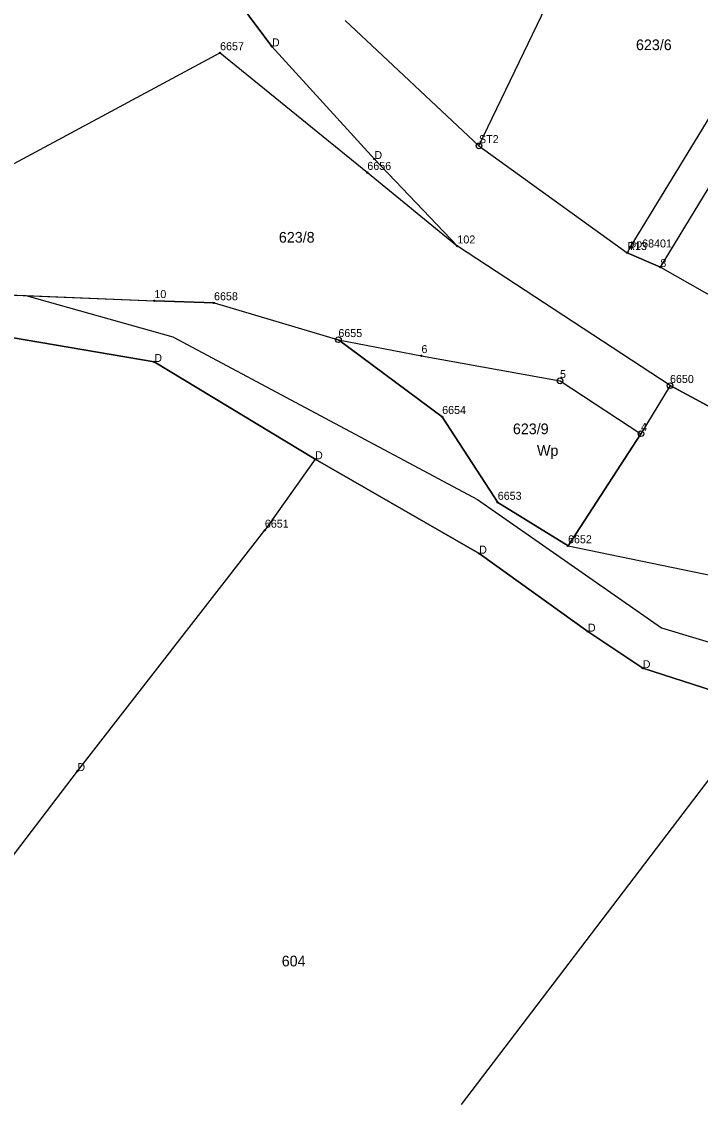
# Model space of a CAD drawing. Extents: x 7465393 to 7466459, y 5491258 to 5492404.
# Drawn here: x 7465961.5 to 7466056.8, y 5491423.8 to 5491575.9 of the extents above; entities that cross this region are included whole.
import ezdxf

# ---------------------------------------------------------------- set-up
doc = ezdxf.new("R2010")
doc.units = 0
for name, color, linetype in [('202-punkt graniczny', 7, 'Continuous'), ('202-punkt graniczny-Atr103', 7, 'Continuous'), ('203-punkt graniczny', 7, 'Continuous'), ('203-punkt graniczny-Atr103', 7, 'Continuous'), ('210-oznaczenie konturu użytku gruntowego', 7, 'Continuous'), ('211-numer działki ewidencyjnej', 7, 'Continuous'), ('217-kontur klasyfikacyjny', 7, 'Continuous'), ('218-kontur użytku gruntowego', 7, 'Continuous'), ('219-działka ewidencyjna', 7, 'Continuous')]:
    doc.layers.add(name, color=color, linetype=linetype)

# ---------------------------------------------------------------- blocks, each defined once
blk = doc.blocks.new('203')
blk.add_circle((0, 0), 0.09)
blk = doc.blocks.new('202')
blk.add_circle((0, 0), 0.4)

msp = doc.modelspace()

# ---------------------------------------------------------------- linework, layer by layer
at = {"layer": '217-kontur klasyfikacyjny'}
for points in [[(7466006.91, 5491576.09), (7466025.72, 5491558.49)], [(7466025.72, 5491558.49), (7466046.56, 5491543.47)], [(7466046.56, 5491543.47), (7466051.21, 5491541.46)], [(7466051.21, 5491541.46), (7466097.56, 5491515.12)], [(7465980.11, 5491528.12), (7465941.89, 5491534.63)], [(7466002.69, 5491514.45), (7465980.11, 5491528.12)], [(7466025.75, 5491501.18), (7466002.69, 5491514.45)], [(7466041.03, 5491490.22), (7466025.75, 5491501.18)], [(7466048.73, 5491485.09), (7466041.03, 5491490.22)], [(7466065.72, 5491479.6), (7466048.73, 5491485.09)]]:
    msp.add_lwpolyline(points, dxfattribs=at)
at = {"layer": '218-kontur użytku gruntowego'}
for points in [[(7465996.64, 5491572.47), (7465974.63, 5491601.95)], [(7466006.91, 5491576.09), (7466025.72, 5491558.49)], [(7466011.03, 5491556.64), (7465996.64, 5491572.47)], [(7466025.72, 5491558.49), (7466046.56, 5491543.47)], [(7466022.69, 5491544.39), (7466011.03, 5491556.64)], [(7466052.56, 5491524.79), (7466022.69, 5491544.39)], [(7466046.56, 5491543.47), (7466051.21, 5491541.46)], [(7466051.21, 5491541.46), (7466097.56, 5491515.12)], [(7465958.19, 5491537.62), (7465962.06, 5491537.46)], [(7465962.06, 5491537.46), (7465980.12, 5491536.72)], [(7465962.06, 5491537.46), (7465982.7, 5491531.67)], [(7465980.12, 5491536.72), (7465988.5, 5491536.41)], [(7465988.5, 5491536.41), (7466005.97, 5491531.25)], [(7465980.11, 5491528.12), (7465941.89, 5491534.63)], [(7465982.7, 5491531.67), (7466025.53, 5491508.79)], [(7466005.97, 5491531.25), (7466017.64, 5491528.99)], [(7466020.55, 5491520.43), (7466005.97, 5491531.25)], [(7466017.64, 5491528.99), (7466037.11, 5491525.47)], [(7466002.69, 5491514.45), (7465980.11, 5491528.12)], [(7466037.11, 5491525.47), (7466048.48, 5491518.04)], [(7466088.4, 5491505.48), (7466052.56, 5491524.79)], [(7466028.36, 5491508.37), (7466020.55, 5491520.43)], [(7466048.48, 5491518.04), (7466038.23, 5491502.27)], [(7466025.75, 5491501.18), (7466002.69, 5491514.45)], [(7466025.53, 5491508.79), (7466051.37, 5491490.77)], [(7466038.23, 5491502.27), (7466028.36, 5491508.37)], [(7466038.23, 5491502.27), (7466083.4, 5491492.98)], [(7466041.03, 5491490.22), (7466025.75, 5491501.18)], [(7466048.73, 5491485.09), (7466041.03, 5491490.22)], [(7466051.37, 5491490.77), (7466091.01, 5491478.79)], [(7466065.72, 5491479.6), (7466048.73, 5491485.09)]]:
    msp.add_lwpolyline(points, dxfattribs=at)
at = {"layer": '219-działka ewidencyjna'}
for points in [[(7465974.63, 5491601.95), (7465996.64, 5491572.47)], [(7466025.72, 5491558.49), (7466045.25, 5491599.04)], [(7466046.97, 5491544.21), (7466071.15, 5491583.85)], [(7466006.91, 5491576.09), (7466025.72, 5491558.49)], [(7465996.64, 5491572.47), (7466011.03, 5491556.64)], [(7465989.35, 5491571.56), (7465947.97, 5491549.31)], [(7465989.35, 5491571.56), (7466010.04, 5491554.73)], [(7466051.21, 5491541.46), (7466063.32, 5491561.29)], [(7466025.72, 5491558.49), (7466046.56, 5491543.47)], [(7466011.03, 5491556.64), (7466022.69, 5491544.39)], [(7466010.04, 5491554.73), (7466022.69, 5491544.39)], [(7466052.56, 5491524.79), (7466022.69, 5491544.39)], [(7466046.97, 5491544.21), (7466046.56, 5491543.47)], [(7466051.21, 5491541.46), (7466046.56, 5491543.47)], [(7466051.21, 5491541.46), (7466097.56, 5491515.12)], [(7465958.19, 5491537.62), (7465980.12, 5491536.72)], [(7465988.5, 5491536.41), (7465980.12, 5491536.72)], [(7465988.5, 5491536.41), (7466005.97, 5491531.25)], [(7465941.89, 5491534.63), (7465980.11, 5491528.12)], [(7466005.97, 5491531.25), (7466017.64, 5491528.99)], [(7466005.97, 5491531.25), (7466020.55, 5491520.43)], [(7466017.64, 5491528.99), (7466037.11, 5491525.47)], [(7465980.11, 5491528.12), (7466002.69, 5491514.45)], [(7466037.11, 5491525.47), (7466048.48, 5491518.04)], [(7466052.56, 5491524.79), (7466048.48, 5491518.04)], [(7466052.56, 5491524.79), (7466088.4, 5491505.48)], [(7466020.55, 5491520.43), (7466028.36, 5491508.37)], [(7466038.23, 5491502.27), (7466048.48, 5491518.04)], [(7466002.69, 5491514.45), (7465995.64, 5491504.46)], [(7466002.69, 5491514.45), (7466025.75, 5491501.18)], [(7466028.36, 5491508.37), (7466038.23, 5491502.27)], [(7465969.3, 5491470.62), (7465995.64, 5491504.46)], [(7466038.23, 5491502.27), (7466083.4, 5491492.98)], [(7466025.75, 5491501.18), (7466041.03, 5491490.22)], [(7466041.03, 5491490.22), (7466048.73, 5491485.09)], [(7466048.73, 5491485.09), (7466065.72, 5491479.6)], [(7466065.72, 5491479.6), (7466023.22, 5491423.79)], [(7465957.71, 5491455.43), (7465969.3, 5491470.62)]]:
    msp.add_lwpolyline(points, dxfattribs=at)

# ---------------------------------------------------------------- block references
at = {"layer": '202-punkt graniczny'}
for p in [(7466025.72, 5491558.49), (7466005.97, 5491531.25), (7466037.11, 5491525.47), (7466052.56, 5491524.79), (7466048.48, 5491518.04)]:
    msp.add_blockref('202', p, dxfattribs=at)
at = {"layer": '203-punkt graniczny'}
for p in [(7465989.35, 5491571.56), (7465996.64, 5491572.47), (7466011.03, 5491556.64), (7466010.04, 5491554.73), (7466022.69, 5491544.39), (7466046.97, 5491544.21), (7466046.56, 5491543.47), (7466051.21, 5491541.46), (7465980.12, 5491536.72), (7465988.5, 5491536.41), (7466017.64, 5491528.99), (7465980.11, 5491528.12), (7466020.55, 5491520.43), (7466002.69, 5491514.45), (7466028.36, 5491508.37), (7465995.64, 5491504.46), (7466038.23, 5491502.27), (7466025.75, 5491501.18), (7466041.03, 5491490.22), (7466048.73, 5491485.09), (7465969.3, 5491470.62)]:
    msp.add_blockref('203', p, dxfattribs=at)

# ---------------------------------------------------------------- texts
at = {"layer": '202-punkt graniczny-Atr103'}
for s, height, p in [('ST2', 1.125, (7466025.72, 5491558.87)), ('6655', 1.125, (7466005.97, 5491531.62)), ('5', 1.12, (7466037.11, 5491525.85)), ('6650', 1.125, (7466052.56, 5491525.17)), ('4', 1.12, (7466048.48, 5491518.42))]:
    msp.add_text(s, height=height, dxfattribs=at).set_placement(p)
at = {"layer": '203-punkt graniczny-Atr103'}
for s, height, p in [('D', 1.12, (7465996.64, 5491572.47)), ('6657', 1.125, (7465989.35, 5491571.93)), ('D', 1.12, (7466011.03, 5491556.64)), ('6656', 1.125, (7466010.04, 5491555.11)), ('102', 1.125, (7466022.69, 5491544.77)), ('R13', 1.125, (7466046.56, 5491543.85)), ('pp68401', 1.125, (7466046.97, 5491544.21)), ('8', 1.12, (7466051.21, 5491541.46)), ('10', 1.125, (7465980.12, 5491537.1)), ('6658', 1.125, (7465988.5, 5491536.79)), ('6', 1.12, (7466017.64, 5491529.37)), ('D', 1.12, (7465980.11, 5491528.12)), ('6654', 1.125, (7466020.55, 5491520.81)), ('D', 1.12, (7466002.69, 5491514.45)), ('6653', 1.125, (7466028.36, 5491508.75)), ('6651', 1.125, (7465995.64, 5491504.83)), ('6652', 1.125, (7466038.23, 5491502.64)), ('D', 1.12, (7466025.75, 5491501.18)), ('D', 1.12, (7466041.03, 5491490.22)), ('D', 1.12, (7466048.73, 5491485.09)), ('D', 1.12, (7465969.3, 5491470.62))]:
    msp.add_text(s, height=height, dxfattribs=at).set_placement(p)
at = {"layer": '210-oznaczenie konturu użytku gruntowego'}
msp.add_text('Wp', height=1.5, dxfattribs=at).set_placement((7466033.87, 5491514.93))
at = {"layer": '211-numer działki ewidencyjnej'}
for s, p in [('623/6', (7466047.78, 5491571.94)), ('623/8', (7465997.61, 5491544.89)), ('623/9', (7466030.49, 5491517.97)), ('604', (7465998.01, 5491443.18))]:
    msp.add_text(s, height=1.5, dxfattribs=at).set_placement(p)

doc.saveas('drawing.dxf')
